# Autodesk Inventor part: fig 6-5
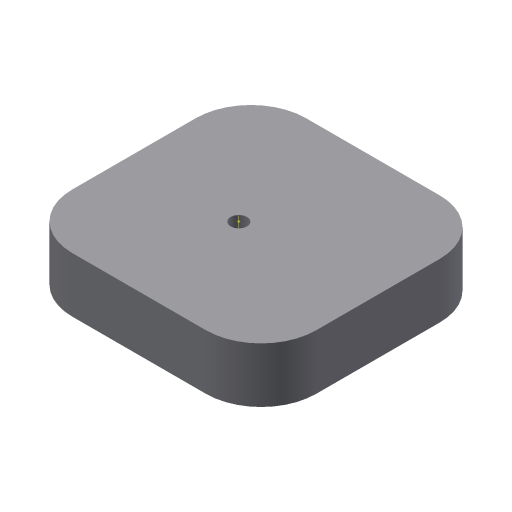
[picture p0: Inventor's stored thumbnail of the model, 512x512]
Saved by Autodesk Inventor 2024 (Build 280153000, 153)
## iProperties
Created: 2004-05
Part Number: fig 6-5
Document SubType Name: Modeling
Designer: CADCIM Technologies
Manufacturer: Standard
Standards Organization: Custom
Density: 1 g/cm^3
Material: Generic
Appearance: Default
Author: CADCIM Technologies
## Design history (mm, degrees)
sketch "Sketch1"
  geometry: L1 (0, 0)-(44.293, 0); L2 (44.293, 0)-(44.293, 42.442); L3 (44.293, 42.442)-(0, 42.442); L4 (0, 42.442)-(0, 0)
  constraints: 8 end point, 2 parallel, 1 horizontal, 1 perpendicular
extrude "Extrusion1" new body sketch "Sketch1" distance "d0" = 10; taper "d1" = 0 deg
fillet "Fillet1" dims "d2" = 10
sketch "Sketch2"
  geometry: 1 further point
sketch "Sketch3"
  geometry: L1 (10, 42.442)-(34.293, 42.442) reference; L2 (0, 10)-(0, 32.442) reference; L3 (34.293, 0)-(10, 0) reference; L4 (44.293, 32.442)-(44.293, 10) reference; A1 r 10 centre (34.293, 32.442) between (44.293, 32.442) and (34.293, 42.442) reference; A2 r 10 centre (10, 32.442) between (10, 42.442) and (0, 32.442) reference; A3 r 10 centre (10, 10) between (0, 10) and (10, 0) reference; A4 r 10 centre (34.293, 10) between (34.293, 0) and (44.293, 10) reference; 1 further point
workaxis "Work Axis1"
  workpoint "Work Point1"
hole "Hole3" diameter "d24" = 3; stored, may be unused: countersink angle "d28" = 90 deg, drill point angle "d30" = 118 deg; dims "d22" = 10, "d23" = 10, "d25" = 6, "d26" = 4, "d27" = 2, "d29" = 8
body "Solid1"
